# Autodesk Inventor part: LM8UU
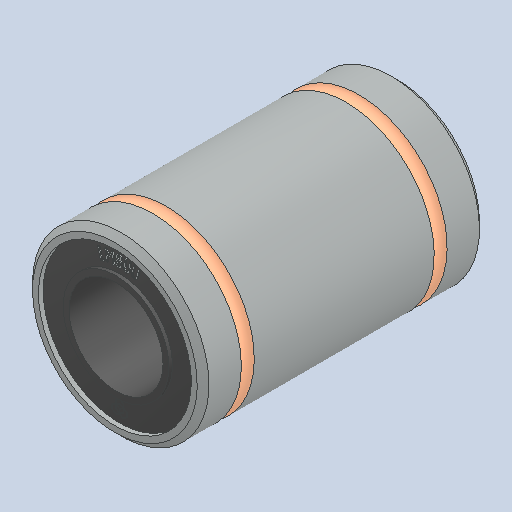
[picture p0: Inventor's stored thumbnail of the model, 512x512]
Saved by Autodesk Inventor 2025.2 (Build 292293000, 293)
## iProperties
Created: 2016-01
Part Number: LM8UU
Material: Generic
Description: STEP AP214
Document SubType Name: Modeling
Designer: BennF
Density: 1 g/cm^3
Appearance: Default
Sending System: SolidWorks 2015
Preprocessor: SwSTEP 2.0
Title: Ëèíåéíûé ïîäøèïíèê, ñåðèÿ LM8UU.STEP
Revision Number: ANY
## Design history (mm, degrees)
feature "LM8UU"
body "Solid1"
